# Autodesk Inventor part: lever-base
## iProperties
Author: E. MOSS
Created: 2001-10
Part Number: lever-base
Document SubType Name: Modeling
Designer: E. MOSS
Control State: 0
Master: False
Checked Out: False
PropertySet Name: Design Tracking Control
Shininess: 64.0
Angle Display Precision: 2
Document Length Units: 11272
Document Angle Units: 11286
Document Time Units: 11279
Document Mass Units: 11290
Document Length Units Precision: 3
Document Angle Units Precision: 2
Compacted: False
PropertySet Name: _Private Model Information
Density: 0.0
Volumn: 0.0
Area: 0.0
PropertySet Name: Model Information
